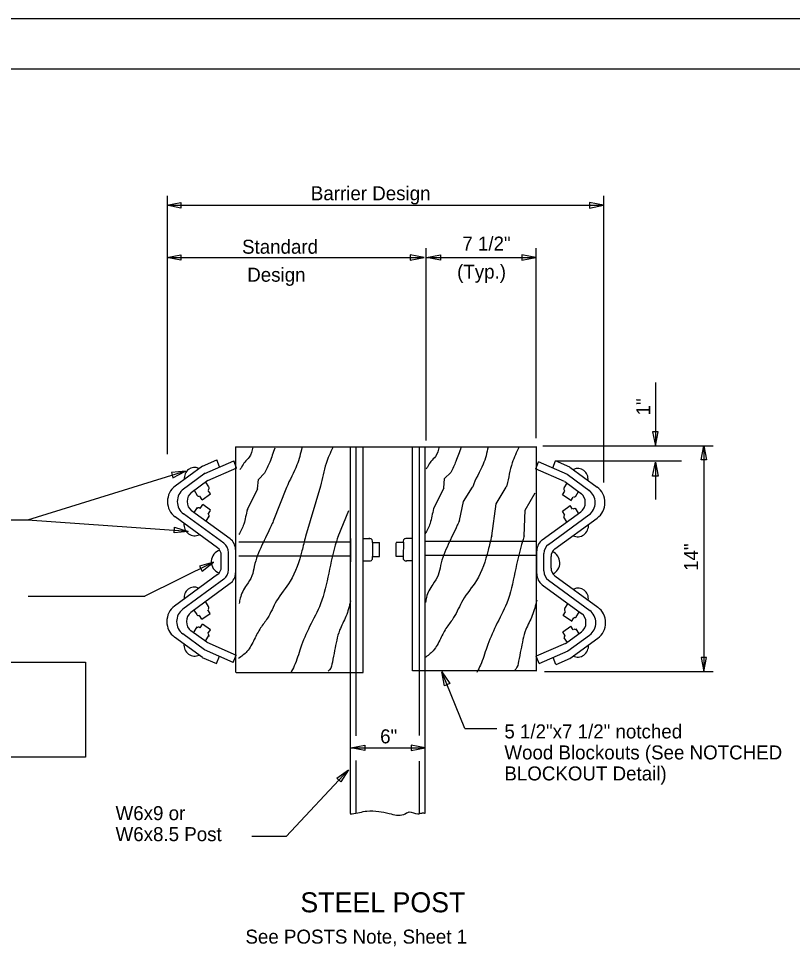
# Model space of a CAD drawing. Extents: x 0 to 34, y 0 to 22.
# Drawn here: x 11.64 to 19.37, y 12.6 to 22 of the extents above; entities that cross this region are included whole.
import ezdxf

# ---------------------------------------------------------------- set-up
doc = ezdxf.new("R2010")
doc.units = 0
for name, color, linetype in [('SH_Border', 7, 'Continuous'), ('SH_Cut_Line', 7, 'Continuous'), ('ST_Details', 7, 'Continuous'), ('ST_Text', 7, 'Continuous')]:
    doc.layers.add(name, color=color, linetype=linetype)

msp = doc.modelspace()

# ---------------------------------------------------------------- linework, layer by layer
at = {"layer": 'SH_Border'}
msp.add_lwpolyline([(1.5, 21.5), (33.5, 21.5), (33.5, 0.5), (1.5, 0.5)], close=True, dxfattribs=at)
at = {"layer": 'SH_Cut_Line'}
msp.add_lwpolyline([(0, 0), (34, 0), (34, 22), (0, 22)], close=True, dxfattribs=at)
at = {"layer": 'ST_Details'}
for p, q in [((13.8045, 17.7204), (16.8155, 17.7204)), ((13.8045, 17.7204), (13.8045, 15.4639)), ((14.9532, 15.4641), (14.9532, 17.7132)), ((15.0099, 15.4641), (15.0099, 17.7132)), ((15.0807, 15.4641), (15.0807, 17.7132)), ((15.5737, 15.4784), (15.5737, 17.7179)), ((15.6445, 15.4784), (15.6445, 17.7179)), ((15.7012, 15.4784), (15.7012, 17.7179)), ((16.8112, 17.7204), (16.8112, 15.4782)), ((13.4719, 17.5269), (13.6158, 17.5897)), ((13.6433, 17.5196), (13.6163, 17.5889)), ((13.4722, 17.5266), (13.1992, 17.3266)), ((13.4967, 17.4539), (13.7861, 17.5802)), ((13.5258, 17.3834), (13.8154, 17.5096)), ((13.8122, 17.5101), (13.7852, 17.5792)), ((17.0938, 17.3726), (16.8043, 17.4989)), ((16.8074, 17.4992), (16.8344, 17.5686)), ((17.1231, 17.4431), (16.8336, 17.5694)), ((16.9764, 17.5089), (17.0034, 17.5781)), ((17.1478, 17.5161), (17.0038, 17.5789)), ((17.1475, 17.5157), (17.4204, 17.3157)), ((13.4992, 17.4554), (13.2692, 17.2867)), ((14.0938, 17.4547), (14.0315, 17.3941)), ((15.8855, 17.3072), (15.8937, 17.4012)), ((15.9561, 17.4619), (15.8937, 17.4012)), ((17.1205, 17.4446), (17.3506, 17.2759)), ((13.525, 17.3829), (13.3583, 17.2607)), ((13.5364, 17.3182), (13.5062, 17.3656)), ((14.0233, 17.3001), (14.0315, 17.3941)), ((14.3129, 17.3119), (14.1808, 16.9761)), ((14.6532, 17.3251), (14.5026, 16.8231)), ((15.8855, 17.3072), (15.7845, 17.1011)), ((17.0891, 17.3096), (17.1192, 17.3569)), ((17.0947, 17.3721), (17.2614, 17.2499)), ((13.4207, 17.2357), (13.3915, 17.2814)), ((13.4693, 17.1892), (13.4462, 17.2256)), ((13.4692, 17.1897), (13.5517, 17.2482)), ((13.5516, 17.2482), (13.5289, 17.2837)), ((14.0233, 17.3001), (13.9212, 17.0892)), ((17.1563, 17.1811), (17.0737, 17.2397)), ((17.0738, 17.2396), (17.0965, 17.2751)), ((17.1561, 17.1807), (17.1792, 17.2169)), ((17.2048, 17.2271), (17.2339, 17.2727)), ((13.4509, 17.1034), (13.4756, 17.1421)), ((13.5541, 17.0844), (13.4754, 17.1419)), ((17.0714, 17.0757), (17.1501, 17.1332)), ((17.1745, 17.0947), (17.1498, 17.1334)), ((13.686, 16.7546), (13.2821, 17.0491)), ((13.7492, 16.7996), (13.3645, 17.0799)), ((13.391, 17.0631), (13.4227, 17.1131)), ((13.509, 16.9771), (13.54, 17.0256)), ((13.5299, 17.0459), (13.5537, 17.0834)), ((14.8283, 16.8231), (14.9367, 17.0819)), ((16.8705, 16.7889), (17.2552, 17.0692)), ((16.9337, 16.7439), (17.3376, 17.0382)), ((17.0956, 17.0372), (17.0717, 17.0749)), ((17.2345, 17.0544), (17.2027, 17.1044)), ((13.6228, 16.7096), (13.1997, 17.0181)), ((16.9969, 16.6989), (17.4201, 17.0072)), ((17.1164, 16.9684), (17.0855, 17.0171)), ((14.9487, 16.7654), (13.8367, 16.7654)), ((14.9547, 16.5689), (14.9547, 16.8014)), ((15.0792, 16.8028), (15.1477, 16.8028)), ((15.1715, 16.7619), (15.2442, 16.7619)), ((15.1715, 16.7619), (15.1725, 16.6218)), ((15.2442, 16.6218), (15.2442, 16.7619)), ((15.4088, 16.6218), (15.4088, 16.7609)), ((15.4816, 16.7619), (15.4098, 16.7619)), ((15.4816, 16.7619), (15.4805, 16.6218)), ((15.5737, 16.8028), (15.5054, 16.8028)), ((16.8109, 16.7724), (15.699, 16.7724)), ((13.732, 16.4887), (13.732, 16.6619)), ((16.8169, 16.4482), (16.8169, 16.6807)), ((16.8877, 16.4779), (16.8877, 16.6511)), ((13.6612, 16.5181), (13.6612, 16.6324)), ((13.732, 16.5699), (13.732, 16.5807)), ((14.9487, 16.6253), (13.8364, 16.6253)), ((15.0792, 16.5783), (15.1388, 16.5783)), ((15.1725, 16.6218), (15.2442, 16.6218)), ((15.4805, 16.6218), (15.4088, 16.6218)), ((15.5737, 16.5783), (15.5142, 16.5783)), ((16.8109, 16.6323), (15.6986, 16.6323)), ((16.8877, 16.5592), (16.8877, 16.5699)), ((16.9585, 16.5072), (16.9585, 16.6217)), ((13.623, 16.4409), (13.1927, 16.1256)), ((13.6862, 16.3962), (13.2751, 16.0947)), ((16.9335, 16.3854), (17.3446, 16.0839)), ((16.9967, 16.4302), (17.4271, 16.1147)), ((13.7495, 16.3512), (13.3577, 16.0641)), ((16.8702, 16.3404), (17.262, 16.0532)), ((13.4182, 16.0409), (13.3892, 16.0866)), ((13.5341, 16.1236), (13.5039, 16.1709)), ((13.5492, 16.0534), (13.5266, 16.0889)), ((17.0947, 16.1031), (17.1248, 16.1504)), ((13.467, 15.9946), (13.4438, 16.0309)), ((13.4668, 15.9949), (13.5493, 16.0536)), ((17.162, 15.9744), (17.0794, 16.0331)), ((17.0795, 16.0329), (17.1022, 16.0684)), ((17.1617, 15.9741), (17.1849, 16.0104)), ((17.2105, 16.0204), (17.2396, 16.0661)), ((13.3886, 15.8684), (13.4203, 15.9184)), ((13.4486, 15.9087), (13.4732, 15.9474)), ((13.5517, 15.8897), (13.473, 15.9472)), ((17.0771, 15.8692), (17.1557, 15.9267)), ((17.1802, 15.8882), (17.1555, 15.9269)), ((17.2402, 15.8479), (17.2084, 15.8979)), ((13.4725, 15.6132), (13.193, 15.8169)), ((13.4932, 15.6892), (13.2755, 15.8479)), ((13.5153, 15.7642), (13.3579, 15.8789)), ((13.5067, 15.7822), (13.5377, 15.8309)), ((13.5275, 15.8512), (13.5514, 15.8887)), ((17.1012, 15.8307), (17.0773, 15.8682)), ((17.1221, 15.7617), (17.0912, 15.8104)), ((17.1043, 15.7534), (17.2617, 15.8681)), ((17.1264, 15.6784), (17.3442, 15.8371)), ((17.1472, 15.6024), (17.4267, 15.8061)), ((13.5153, 15.7646), (13.8091, 15.6366)), ((17.1043, 15.7537), (16.8107, 15.6257)), ((13.4702, 15.6141), (13.6142, 15.5512)), ((13.7811, 15.5634), (13.4917, 15.6897)), ((13.6132, 15.5516), (13.6416, 15.6242)), ((13.7802, 15.5634), (13.809, 15.6371)), ((16.8394, 15.5526), (16.8107, 15.6262)), ((16.8386, 15.5526), (17.1281, 15.6789)), ((17.0064, 15.5409), (16.9781, 15.6134)), ((17.1495, 15.6032), (17.0056, 15.5406)), ((13.8095, 15.4641), (15.0807, 15.4641)), ((14.9532, 14.0519), (14.9532, 15.4641)), ((15.0099, 14.8304), (15.0099, 15.4641)), ((16.8155, 15.4784), (15.5737, 15.4784)), ((15.6445, 14.8326), (15.6445, 15.4784)), ((15.7012, 14.0566), (15.7012, 15.4784)), ((15.0099, 14.0519), (15.0099, 14.5829)), ((15.6445, 14.0566), (15.6445, 14.5742))]:
    msp.add_line(p, q, dxfattribs=at)
for points in [[(16.043, 16.9832), (16.0821, 17.1722), (16.1742, 17.3162)], [(16.3647, 16.8301), (16.4097, 17.1497), (16.5112, 17.3162)], [(16.6906, 16.8301), (16.701, 17.0854), (16.799, 17.2589)]]:
    msp.add_lwpolyline(points, dxfattribs=at)
for centre, major_axis, start_param, end_param in [((13.3919, 17.4076), (0, -0.1065), 2.687211, 4.851441), ((17.2278, 17.3968), (0, -0.1065), 1.431744, 3.595974), ((13.3001, 17.1724), (0, -0.1875), 3.747084, 5.680264), ((13.5205, 17.3058), (0, 0.0198), 3.70437, 5.352473), ((17.1049, 17.2972), (0, 0.0198), 0.930712, 2.578815), ((17.3196, 17.1616), (0, -0.1875), 0.602921, 2.536101), ((13.3624, 17.1725), (0, -0.15), 3.747137, 5.680324), ((13.4248, 17.1726), (0, -0.1125), 3.747102, 5.680297), ((13.4335, 17.2463), (0, -0.0195), 5.247458, 6.879592), ((17.192, 17.2377), (0, -0.0195), 5.686779, 7.318912), ((17.1949, 17.1618), (0, -0.1125), 0.602888, 2.536083), ((17.2573, 17.1617), (0, -0.15), 0.602861, 2.536048), ((13.4352, 17.0899), (0, 0.021), 5.452301, 7.118326), ((13.5208, 17.0274), (0, 0.021), 4.196406, 5.73538), ((17.1046, 17.0188), (0, 0.021), 0.547805, 2.086779), ((17.1903, 17.0813), (0, 0.021), 5.448045, 7.11407), ((13.3951, 16.9451), (0, -0.115), 4.640651, 6.714317), ((17.2246, 16.9343), (0, -0.115), 5.852054, 7.925719), ((13.6257, 16.662), (0, 0.1125), 4.712389, 5.68034), ((13.6789, 16.6916), (0, 0.1312), 4.712389, 5.680267), ((15.146, 16.7733), (0, -0.0298), 2.729343, 3.43401), ((15.1449, 16.7725), (0, 0.03), 4.35702, 6.237266), ((15.146, 16.7733), (0, -0.0298), 1.431351, 1.439211), ((15.5081, 16.7725), (0, 0.03), 0.045919, 1.926166), ((15.507, 16.7733), (0, -0.0298), 4.843974, 4.851834), ((15.507, 16.7733), (0, -0.0298), 2.849176, 3.553842), ((16.9408, 16.6808), (0, 0.1312), 0.602918, 1.570796), ((16.994, 16.6512), (0, 0.1125), 0.602846, 1.570796), ((13.6719, 16.5699), (0, -0.1171), 3.363241, 5.976631), ((13.5726, 16.6324), (0, 0.0937), 4.712389, 5.680377), ((17.0471, 16.6216), (0, 0.0937), 0.602808, 1.570796), ((16.9331, 16.5587), (0, -0.1192), 0.40519, 2.779828), ((15.1438, 16.6101), (0, -0.0326), 6.093782, 8.224205), ((15.5092, 16.6101), (0, -0.0326), 4.342165, 6.472589), ((13.5726, 16.5181), (0, -0.0937), 0.605563, 1.570796), ((13.6257, 16.4886), (0, -0.1125), 0.605651, 1.570796), ((13.6789, 16.4591), (0, -0.1312), 0.605566, 1.570796), ((16.994, 16.4778), (0, -0.1125), 4.712389, 5.677535), ((17.0471, 16.5073), (0, -0.0937), 4.712389, 5.677623), ((16.9408, 16.4483), (0, -0.1312), 4.712389, 5.677619), ((13.3888, 16.2107), (0, -0.1065), 2.687211, 4.851441), ((17.2309, 16.1999), (0, -0.1065), 1.431744, 3.595974), ((13.2934, 15.9714), (0, -0.1875), 3.747091, 5.68028), ((13.3558, 15.9715), (0, -0.15), 3.747115, 5.680355), ((13.5182, 16.1111), (0, 0.0198), 3.70437, 5.352473), ((17.1106, 16.0906), (0, 0.0198), 0.930712, 2.578815), ((17.264, 15.9607), (0, -0.15), 0.602831, 2.53607), ((17.3263, 15.9606), (0, -0.1875), 0.602905, 2.536094), ((13.4182, 15.9716), (0, -0.1125), 3.747102, 5.680258), ((13.4311, 16.0516), (0, -0.0195), 5.247458, 6.879592), ((17.1976, 16.0311), (0, -0.0195), 5.686779, 7.318912), ((17.2015, 15.9608), (0, -0.1125), 0.602927, 2.536083), ((13.4328, 15.8952), (0, 0.021), 5.452301, 7.118326), ((17.196, 15.8747), (0, 0.021), 5.448045, 7.11407), ((13.5185, 15.8327), (0, 0.021), 4.196406, 5.73538), ((17.1103, 15.8122), (0, 0.021), 0.547805, 2.086779), ((13.3951, 15.7418), (0, -0.115), 4.640651, 6.714317), ((17.2246, 15.731), (0, -0.115), 5.852054, 7.925719)]:
    msp.add_ellipse(centre, major_axis=major_axis, ratio=0.944544, start_param=start_param, end_param=end_param, dxfattribs=at)
for points in [[(13.977, 17.7161), (13.9407, 17.6152), (13.8952, 17.5671), (13.8635, 17.5142), (13.8472, 17.4884)], [(14.195, 17.7066), (14.145, 17.5671), (14.0938, 17.4547)], [(14.4674, 17.7114), (14.4175, 17.5382), (14.3131, 17.3122), (14.3119, 17.3091)], [(14.7762, 17.7114), (14.7081, 17.5527), (14.6536, 17.3267), (14.6489, 17.3091)], [(15.8392, 17.7232), (15.8029, 17.6224), (15.7574, 17.5742), (15.7257, 17.5214), (15.7095, 17.4956)], [(16.0572, 17.7137), (16.0072, 17.5742), (15.9561, 17.4619)], [(16.3297, 17.7186), (16.2797, 17.5454), (16.1752, 17.3194), (16.1742, 17.3162)], [(16.6384, 17.7186), (16.5703, 17.5599), (16.5158, 17.3339), (16.5112, 17.3162)], [(13.9223, 17.0939), (13.9044, 17.0191), (13.8862, 16.9469), (13.8362, 16.8412)], [(15.7845, 17.1011), (15.7666, 17.0262), (15.7484, 16.9541), (15.6984, 16.8482)], [(14.1808, 16.9761), (14.1587, 16.9277), (14.0677, 16.7354), (13.9907, 16.5239), (13.968, 16.4277), (13.9135, 16.3364), (13.8499, 16.2067), (13.8407, 16.1537)], [(16.043, 16.9832), (16.0208, 16.9349), (15.93, 16.7426), (15.8528, 16.5311), (15.8302, 16.4349), (15.7757, 16.3436), (15.7121, 16.2137), (15.703, 16.1609)], [(14.5026, 16.8231), (14.4674, 16.6777), (14.3494, 16.3749), (14.2132, 16.1777), (14.1222, 16.0047), (14.0542, 15.9086), (13.9907, 15.7932), (13.918, 15.6731), (13.8317, 15.6009)], [(14.8283, 16.8231), (14.8125, 16.7739), (14.7352, 16.4566), (14.6536, 16.1489), (14.5446, 15.9231), (14.4537, 15.7066), (14.3902, 15.5287), (14.3539, 15.4567)], [(16.3647, 16.8301), (16.3297, 16.6849), (16.2116, 16.3821), (16.0753, 16.1849), (15.9845, 16.0119), (15.9164, 15.9157), (15.8528, 15.8004), (15.7802, 15.6802), (15.6939, 15.6081)], [(16.6906, 16.8301), (16.6747, 16.7811), (16.5975, 16.4637), (16.5158, 16.1561), (16.4068, 15.9302), (16.316, 15.7137), (16.2524, 15.5359), (16.2162, 15.4639)], [(14.9532, 16.1777), (14.9079, 16.0241), (14.8442, 15.8846), (14.7944, 15.6826), (14.7717, 15.5672), (14.7444, 15.4902), (14.7307, 15.4759)], [(16.8155, 16.1849), (16.7702, 16.0311), (16.7065, 15.8917), (16.6566, 15.6897), (16.6338, 15.5744), (16.6067, 15.4974), (16.593, 15.4831)], [(14.9503, 14.0496), (14.969, 14.0502), (15.1172, 14.0771), (15.2352, 14.0722), (15.3397, 14.0531), (15.485, 14.0434), (15.5395, 14.0674), (15.6258, 14.0482), (15.6657, 14.0566), (15.7012, 14.0566)]]:
    msp.add_spline(points, degree=3, dxfattribs=at)
at = {"layer": 'ST_Text'}
for p, q in [((13.1181, 20.2294), (13.1182, 17.6452)), ((17.4818, 20.2294), (17.4818, 17.3636)), ((13.1161, 20.1349), (17.4818, 20.1349)), ((15.7064, 19.7074), (15.7064, 17.7811)), ((16.8052, 19.7074), (16.8052, 17.8052)), ((13.1177, 19.6129), (13.6959, 19.6129)), ((13.6959, 19.6129), (15.6893, 19.6129)), ((15.7121, 19.6129), (16.0798, 19.6129)), ((16.0798, 19.6129), (16.8052, 19.6129)), ((18.0021, 18.3635), (18.0021, 17.7281)), ((16.8747, 17.7281), (18.5807, 17.7281)), ((18.4862, 17.7281), (18.4862, 17.0224)), ((17.0038, 17.5789), (18.2621, 17.5789)), ((18.0021, 17.5662), (18.0021, 17.1912)), ((13.3303, 16.8739), (11.7236, 16.9862)), ((18.4862, 17.0224), (18.4862, 15.4734)), ((13.5814, 16.5672), (12.8962, 16.2255)), ((11.7312, 16.2255), (12.8962, 16.2255)), ((16.0947, 14.9026), (15.8677, 15.4704)), ((16.8926, 15.4734), (18.5807, 15.4734)), ((16.0947, 14.9026), (16.4156, 14.9026)), ((14.9532, 14.7091), (15.6984, 14.7091)), ((14.9569, 14.7091), (15.1444, 14.7091)), ((14.3082, 13.8227), (14.9325, 14.4876)), ((14.3082, 13.8227), (13.9654, 13.8227))]:
    msp.add_line(p, q, dxfattribs=at)
for points in [[(13.2561, 20.1069), (13.1161, 20.1349), (13.2561, 20.1629)], [(17.3418, 20.1069), (17.4818, 20.1349), (17.3418, 20.1629)], [(13.2577, 19.5849), (13.1177, 19.6129), (13.2577, 19.6409)], [(15.5493, 19.5849), (15.6893, 19.6129), (15.5493, 19.6409)], [(15.8521, 19.5849), (15.7121, 19.6129), (15.8521, 19.6409)], [(16.6652, 19.5849), (16.8052, 19.6129), (16.6652, 19.6409)], [(17.9741, 17.8681), (18.0021, 17.7281), (18.0301, 17.8681)], [(18.4582, 17.5881), (18.4862, 17.7281), (18.5142, 17.5881)], [(17.9741, 17.4262), (18.0021, 17.5662), (18.0301, 17.4262)], [(13.1775, 17.4101), (13.3044, 17.4756), (13.1621, 17.4639)], [(13.194, 16.9164), (13.3303, 16.8739), (13.1881, 16.8607)], [(13.471, 16.4768), (13.5814, 16.5672), (13.4447, 16.5262)], [(18.4582, 15.6134), (18.4862, 15.4734), (18.5142, 15.6134)], [(9.5197, 15.5651), (12.3046, 15.5651), (12.3046, 14.6162), (9.5197, 14.6162)], [(15.8942, 15.3301), (15.8677, 15.4704), (15.9461, 15.3511)], [(15.0969, 14.6811), (14.9569, 14.7091), (15.0969, 14.7371)], [(15.5584, 14.6811), (15.6984, 14.7091), (15.5584, 14.7371)], [(14.8151, 14.4063), (14.9325, 14.4876), (14.8554, 14.3674)]]:
    msp.add_lwpolyline(points, close=True, dxfattribs=at)
msp.add_lwpolyline([(13.3044, 17.4756), (11.7236, 16.9862), (11.4729, 16.9862)], dxfattribs=at)

# ---------------------------------------------------------------- texts
for s, rotation, p in [('Barrier Design', 360, (14.5566, 20.1851)), ('Standard', 360, (13.8685, 19.6506)), (' 7 1/2"', 360, (16.0193, 19.6816)), (' Design', 360, (13.8685, 19.3706)), ('(Typ.)', 360, (16.0193, 19.4016)), ('1" ', 90, (17.951, 18.0337)), ('14" ', 90, (18.4287, 16.4783)), ('6" ', 360, (15.2495, 14.7539)), ('5 1/2"x7 1/2" notched', 360, (16.4917, 14.8031)), ('Wood Blockouts (See NOTCHED', 360, (16.4917, 14.5931)), ('BLOCKOUT Detail)', 360, (16.4917, 14.3831)), ('W6x9 or', 360, (12.6039, 13.9858)), ('W6x8.5 Post', 360, (12.6039, 13.7758)), ('See POSTS Note, Sheet 1', 360, (13.9025, 12.7508))]:
    msp.add_text(s, height=0.14, rotation=rotation, dxfattribs=at).set_placement(p)
msp.add_text('STEEL POST', height=0.2, dxfattribs=at).set_placement((14.4517, 13.0641))

doc.saveas('drawing.dxf')
